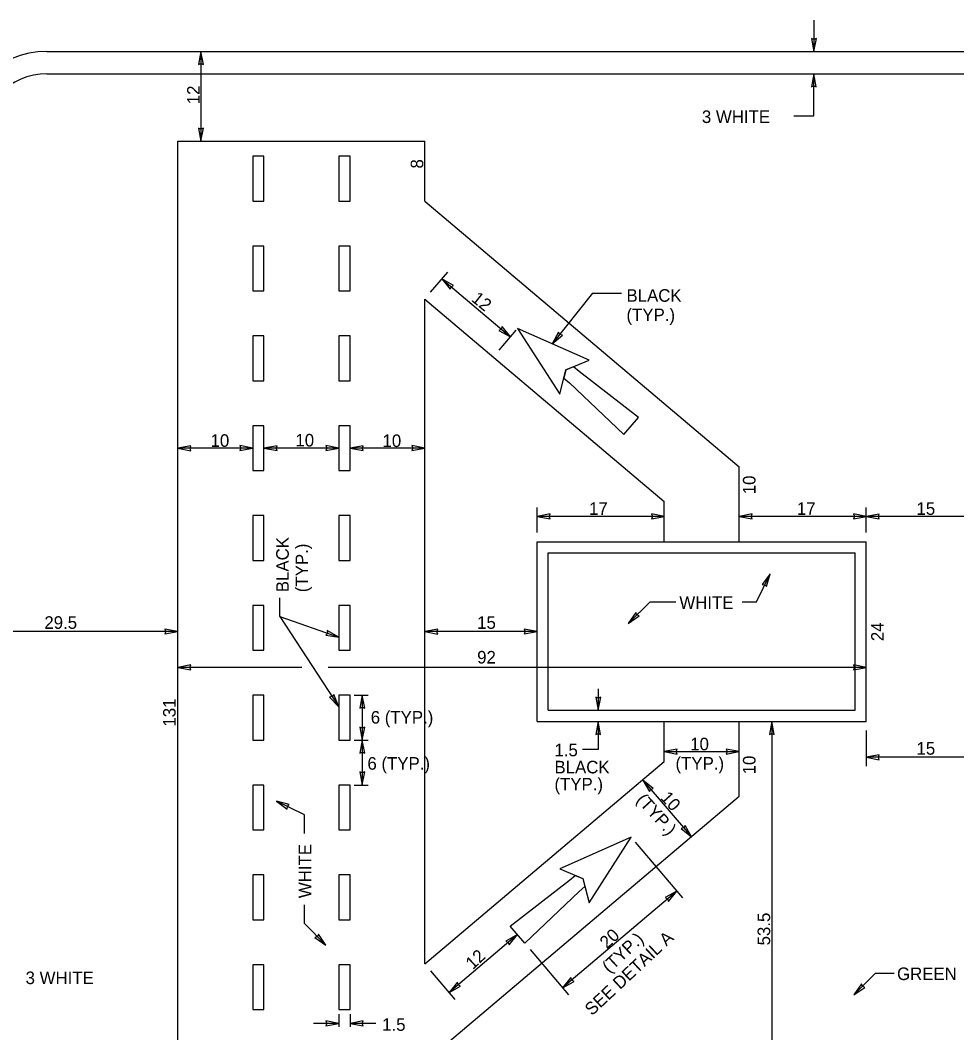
# Model space of a CAD drawing. Extents: x 319701 to 320014, y 1621790 to 1621996.
# Drawn here: x 319807.6 to 319911.9, y 1621877.3 to 1621990 of the extents above; entities that cross this region are included whole.
import ezdxf

# ---------------------------------------------------------------- set-up
doc = ezdxf.new("R2010")
doc.units = 0
for name, color, linetype in [('1', 7, 'Continuous'), ('40', 7, 'Continuous'), ('48', 7, 'Continuous'), ('52', 7, 'Continuous')]:
    doc.layers.add(name, color=color, linetype=linetype)

msp = doc.modelspace()

# ---------------------------------------------------------------- linework, layer by layer
at = {"layer": '1'}
for p, q in [((319810.55, 1621986.54), (319970.55, 1621986.54)), ((319810.55, 1621984.04), (319970.55, 1621984.04)), ((319825.14, 1621976.54), (319852.63, 1621976.54)), ((319825.14, 1621867.37), (319825.14, 1621976.54)), ((319852.63, 1621969.87), (319852.63, 1621976.54)), ((319852.63, 1621969.87), (319887.63, 1621940.29)), ((319852.63, 1621958.96), (319879.3, 1621936.42)), ((319852.63, 1621884.95), (319852.63, 1621958.96)), ((319887.63, 1621931.96), (319887.63, 1621940.29)), ((319879.3, 1621931.96), (319879.3, 1621936.42)), ((319865.13, 1621911.96), (319865.13, 1621931.96)), ((319865.13, 1621931.96), (319901.8, 1621931.96)), ((319901.8, 1621911.96), (319901.8, 1621931.96)), ((319866.38, 1621930.71), (319900.55, 1621930.71)), ((319866.38, 1621913.21), (319866.38, 1621930.71)), ((319900.55, 1621913.21), (319900.55, 1621930.71)), ((319866.38, 1621913.21), (319900.55, 1621913.21)), ((319865.13, 1621911.96), (319901.8, 1621911.96)), ((319879.3, 1621907.49), (319879.3, 1621911.96)), ((319887.63, 1621903.62), (319887.63, 1621911.96)), ((319852.63, 1621884.95), (319879.3, 1621907.49)), ((319852.63, 1621874.04), (319887.63, 1621903.62))]:
    msp.add_line(p, q, dxfattribs=at)
for radius in [10, 7.5]:
    msp.add_arc((319810.55, 1621976.54), radius, 90, 180, dxfattribs=at)
at = {"layer": '40'}
for p, q in [((319834.72, 1621974.87), (319833.47, 1621974.87)), ((319833.47, 1621974.87), (319833.47, 1621969.87)), ((319834.72, 1621969.87), (319834.72, 1621974.87)), ((319844.3, 1621974.87), (319843.05, 1621974.87)), ((319843.05, 1621974.87), (319843.05, 1621969.87)), ((319844.3, 1621969.87), (319844.3, 1621974.87)), ((319833.47, 1621969.87), (319834.72, 1621969.87)), ((319843.05, 1621969.87), (319844.3, 1621969.87)), ((319834.72, 1621964.87), (319833.47, 1621964.87)), ((319833.47, 1621964.87), (319833.47, 1621959.87)), ((319834.72, 1621959.87), (319834.72, 1621964.87)), ((319844.3, 1621964.87), (319843.05, 1621964.87)), ((319843.05, 1621964.87), (319843.05, 1621959.87)), ((319844.3, 1621959.87), (319844.3, 1621964.87)), ((319833.47, 1621959.87), (319834.72, 1621959.87)), ((319843.05, 1621959.87), (319844.3, 1621959.87)), ((319862.96, 1621955.69), (319867.66, 1621948.37)), ((319870.92, 1621952.17), (319862.96, 1621955.69)), ((319834.72, 1621954.87), (319833.47, 1621954.87)), ((319833.47, 1621954.87), (319833.47, 1621949.87)), ((319834.72, 1621949.87), (319834.72, 1621954.87)), ((319844.3, 1621954.87), (319843.05, 1621954.87)), ((319843.05, 1621954.87), (319843.05, 1621949.87)), ((319844.3, 1621949.87), (319844.3, 1621954.87)), ((319868.34, 1621951.08), (319870.92, 1621952.17)), ((319867.66, 1621948.37), (319868.34, 1621951.08)), ((319868.34, 1621951.08), (319868.11, 1621950.18)), ((319869.2, 1621951.44), (319868.34, 1621951.08)), ((319869.83, 1621950.9), (319869.2, 1621951.44)), ((319876.43, 1621945.79), (319869.83, 1621950.9)), ((319833.47, 1621949.87), (319834.72, 1621949.87)), ((319843.05, 1621949.87), (319844.3, 1621949.87)), ((319868.11, 1621950.18), (319868.75, 1621949.63)), ((319868.75, 1621949.63), (319874.8, 1621943.89)), ((319874.8, 1621943.89), (319876.43, 1621945.79)), ((319834.72, 1621944.87), (319833.47, 1621944.87)), ((319833.47, 1621944.87), (319833.47, 1621939.87)), ((319834.72, 1621939.87), (319834.72, 1621944.87)), ((319844.3, 1621944.87), (319843.05, 1621944.87)), ((319843.05, 1621944.87), (319843.05, 1621939.87)), ((319844.3, 1621939.87), (319844.3, 1621944.87)), ((319833.47, 1621939.87), (319834.72, 1621939.87)), ((319843.05, 1621939.87), (319844.3, 1621939.87)), ((319834.72, 1621934.87), (319833.47, 1621934.87)), ((319833.47, 1621934.87), (319833.47, 1621929.87)), ((319834.72, 1621929.87), (319834.72, 1621934.87)), ((319844.3, 1621934.87), (319843.05, 1621934.87)), ((319843.05, 1621934.87), (319843.05, 1621929.87)), ((319844.3, 1621929.87), (319844.3, 1621934.87)), ((319833.47, 1621929.87), (319834.72, 1621929.87)), ((319843.05, 1621929.87), (319844.3, 1621929.87)), ((319834.72, 1621924.87), (319833.47, 1621924.87)), ((319833.47, 1621924.87), (319833.47, 1621919.87)), ((319834.72, 1621919.87), (319834.72, 1621924.87)), ((319844.3, 1621924.87), (319843.05, 1621924.87)), ((319843.05, 1621924.87), (319843.05, 1621919.87)), ((319844.3, 1621919.87), (319844.3, 1621924.87)), ((319833.47, 1621919.87), (319834.72, 1621919.87)), ((319843.05, 1621919.87), (319844.3, 1621919.87)), ((319834.72, 1621914.87), (319833.47, 1621914.87)), ((319833.47, 1621914.87), (319833.47, 1621909.87)), ((319834.72, 1621909.87), (319834.72, 1621914.87)), ((319844.3, 1621914.87), (319843.05, 1621914.87)), ((319843.05, 1621914.87), (319843.05, 1621909.87)), ((319844.3, 1621909.87), (319844.3, 1621914.87)), ((319833.47, 1621909.87), (319834.72, 1621909.87)), ((319843.05, 1621909.87), (319844.3, 1621909.87)), ((319834.72, 1621904.87), (319833.47, 1621904.87)), ((319833.47, 1621904.87), (319833.47, 1621899.87)), ((319834.72, 1621899.87), (319834.72, 1621904.87)), ((319844.3, 1621904.87), (319843.05, 1621904.87)), ((319843.05, 1621904.87), (319843.05, 1621899.87)), ((319844.3, 1621899.87), (319844.3, 1621904.87)), ((319833.47, 1621899.87), (319834.72, 1621899.87)), ((319843.05, 1621899.87), (319844.3, 1621899.87)), ((319875.62, 1621899.07), (319867.66, 1621895.55)), ((319870.92, 1621891.75), (319875.62, 1621899.07)), ((319834.72, 1621894.87), (319833.47, 1621894.87)), ((319833.47, 1621894.87), (319833.47, 1621889.87)), ((319834.72, 1621889.87), (319834.72, 1621894.87)), ((319844.3, 1621894.87), (319843.05, 1621894.87)), ((319843.05, 1621894.87), (319843.05, 1621889.87)), ((319844.3, 1621889.87), (319844.3, 1621894.87)), ((319867.66, 1621895.55), (319870.24, 1621894.46)), ((319868.75, 1621894.28), (319869.38, 1621894.82)), ((319869.38, 1621894.82), (319870.24, 1621894.46)), ((319862.15, 1621889.17), (319868.75, 1621894.28)), ((319870.46, 1621893.56), (319869.83, 1621893.02)), ((319870.24, 1621894.46), (319870.46, 1621893.56)), ((319870.24, 1621894.46), (319870.92, 1621891.75)), ((319869.83, 1621893.02), (319863.77, 1621887.28)), ((319833.47, 1621889.87), (319834.72, 1621889.87)), ((319843.05, 1621889.87), (319844.3, 1621889.87)), ((319863.77, 1621887.28), (319862.15, 1621889.17)), ((319834.72, 1621884.87), (319833.47, 1621884.87)), ((319833.47, 1621884.87), (319833.47, 1621879.87)), ((319834.72, 1621879.87), (319834.72, 1621884.87)), ((319844.3, 1621884.87), (319843.05, 1621884.87)), ((319843.05, 1621884.87), (319843.05, 1621879.87)), ((319844.3, 1621879.87), (319844.3, 1621884.87)), ((319833.47, 1621879.87), (319834.72, 1621879.87)), ((319843.05, 1621879.87), (319844.3, 1621879.87))]:
    msp.add_line(p, q, dxfattribs=at)
at = {"layer": '48'}
for p, q in [((319895.97, 1621990.01), (319895.97, 1621986.54)), ((319827.7, 1621986.54), (319827.7, 1621976.54)), ((319895.97, 1621979.38), (319895.97, 1621984.04)), ((319893.72, 1621979.38), (319895.97, 1621979.38)), ((319853.28, 1621959.73), (319855.18, 1621961.97)), ((319854.53, 1621961.21), (319862.17, 1621954.75)), ((319871.32, 1621959.64), (319866.83, 1621953.98)), ((319871.32, 1621959.64), (319874.53, 1621959.64)), ((319860.92, 1621953.27), (319862.81, 1621955.52)), ((319833.47, 1621942.37), (319825.14, 1621942.37)), ((319843.05, 1621942.37), (319834.72, 1621942.37)), ((319852.63, 1621942.37), (319844.3, 1621942.37)), ((319865.13, 1621932.97), (319865.13, 1621935.78)), ((319901.8, 1621932.97), (319901.8, 1621935.78)), ((319879.3, 1621934.78), (319865.13, 1621934.78)), ((319901.8, 1621934.78), (319887.63, 1621934.78)), ((319914.3, 1621934.78), (319901.8, 1621934.78)), ((319889.57, 1621925.27), (319891.11, 1621928.38)), ((319836.47, 1621923.64), (319836.47, 1621925.71)), ((319877.71, 1621925.27), (319875.29, 1621922.87)), ((319877.71, 1621925.27), (319880.57, 1621925.27)), ((319887.96, 1621925.27), (319889.57, 1621925.27)), ((319836.47, 1621923.64), (319843.05, 1621921.33)), ((319836.47, 1621923.64), (319843.05, 1621913.58)), ((319825.14, 1621921.96), (319800.55, 1621921.96)), ((319865.13, 1621921.96), (319852.63, 1621921.96)), ((319838.93, 1621917.97), (319825.14, 1621917.97)), ((319901.8, 1621917.97), (319841.86, 1621917.97)), ((319844.76, 1621914.87), (319846.33, 1621914.87)), ((319845.66, 1621914.87), (319845.66, 1621909.87)), ((319871.95, 1621915.58), (319871.95, 1621913.21)), ((319871.95, 1621911.96), (319871.95, 1621908.84)), ((319891.29, 1621911.96), (319891.29, 1621867.37)), ((319901.8, 1621910.96), (319901.8, 1621906.98)), ((319844.76, 1621909.87), (319846.33, 1621909.87)), ((319845.66, 1621909.87), (319845.66, 1621904.87)), ((319871.95, 1621908.84), (319870.21, 1621908.84)), ((319879.3, 1621908.59), (319887.63, 1621908.59)), ((319914.3, 1621907.98), (319901.8, 1621907.98)), ((319844.76, 1621904.87), (319846.33, 1621904.87)), ((319876.92, 1621905.42), (319882.34, 1621899.09)), ((319839.23, 1621901.55), (319836.12, 1621903.09)), ((319839.23, 1621899.47), (319839.23, 1621901.55)), ((319876.07, 1621898.53), (319881.34, 1621892.3)), ((319880.7, 1621893.06), (319867.98, 1621882.29)), ((319839.23, 1621889.46), (319839.23, 1621891.53)), ((319839.23, 1621889.46), (319841.62, 1621887.04)), ((319862.96, 1621888.23), (319855.33, 1621881.76)), ((319864.35, 1621886.58), (319868.63, 1621881.52)), ((319853.28, 1621884.19), (319855.98, 1621881)), ((319902.83, 1621883.92), (319900.42, 1621881.53)), ((319902.83, 1621883.92), (319904.91, 1621883.92)), ((319843.05, 1621879.37), (319843.05, 1621877.96)), ((319844.3, 1621879.37), (319844.3, 1621877.96)), ((319843.05, 1621878.33), (319840.24, 1621878.33)), ((319847.17, 1621878.33), (319844.3, 1621878.33))]:
    msp.add_line(p, q, dxfattribs=at)
at = {"layer": '52'}
for p, q in [((319895.96, 1621987.88), (319895.69, 1621987.99)), ((319895.69, 1621987.99), (319895.96, 1621986.54)), ((319895.96, 1621986.54), (319896.24, 1621987.99)), ((319896.24, 1621987.99), (319895.96, 1621987.88)), ((319827.7, 1621986.54), (319827.42, 1621985.09)), ((319827.97, 1621985.09), (319827.7, 1621986.54)), ((319827.42, 1621985.09), (319827.7, 1621985.2)), ((319827.7, 1621985.2), (319827.97, 1621985.09)), ((319895.96, 1621984.04), (319895.68, 1621982.59)), ((319896.23, 1621982.59), (319895.96, 1621984.04)), ((319895.68, 1621982.59), (319895.96, 1621982.7)), ((319895.96, 1621982.7), (319896.23, 1621982.59)), ((319827.7, 1621977.88), (319827.43, 1621977.99)), ((319827.43, 1621977.99), (319827.7, 1621976.54)), ((319827.7, 1621976.54), (319827.98, 1621977.99)), ((319827.98, 1621977.99), (319827.7, 1621977.88)), ((319854.53, 1621961.21), (319855.45, 1621960.06)), ((319855.81, 1621960.48), (319854.53, 1621961.21)), ((319855.45, 1621960.06), (319855.55, 1621960.34)), ((319855.55, 1621960.34), (319855.81, 1621960.48)), ((319861.14, 1621955.62), (319860.88, 1621955.48)), ((319860.88, 1621955.48), (319862.16, 1621954.75)), ((319861.24, 1621955.9), (319861.14, 1621955.62)), ((319862.16, 1621954.75), (319861.24, 1621955.9)), ((319867.51, 1621955.28), (319866.83, 1621953.98)), ((319866.83, 1621953.98), (319867.95, 1621954.94)), ((319867.66, 1621955.03), (319867.51, 1621955.28)), ((319867.95, 1621954.94), (319867.66, 1621955.03)), ((319826.59, 1621942.64), (319825.14, 1621942.37)), ((319825.14, 1621942.37), (319826.59, 1621942.09)), ((319826.48, 1621942.37), (319826.59, 1621942.64)), ((319826.59, 1621942.09), (319826.48, 1621942.37)), ((319833.47, 1621942.38), (319832.02, 1621942.66)), ((319832.02, 1621942.66), (319832.13, 1621942.38)), ((319832.13, 1621942.38), (319832.02, 1621942.11)), ((319832.02, 1621942.11), (319833.47, 1621942.38)), ((319836.17, 1621942.65), (319834.72, 1621942.38)), ((319834.72, 1621942.38), (319836.17, 1621942.1)), ((319836.06, 1621942.38), (319836.17, 1621942.65)), ((319836.17, 1621942.1), (319836.06, 1621942.38)), ((319843.05, 1621942.38), (319841.6, 1621942.66)), ((319841.6, 1621942.66), (319841.71, 1621942.38)), ((319841.71, 1621942.38), (319841.6, 1621942.11)), ((319841.6, 1621942.11), (319843.05, 1621942.38)), ((319845.75, 1621942.65), (319844.3, 1621942.38)), ((319844.3, 1621942.38), (319845.75, 1621942.1)), ((319845.64, 1621942.38), (319845.75, 1621942.65)), ((319845.75, 1621942.1), (319845.64, 1621942.38)), ((319852.63, 1621942.38), (319851.18, 1621942.66)), ((319851.18, 1621942.66), (319851.29, 1621942.38)), ((319851.29, 1621942.38), (319851.18, 1621942.11)), ((319851.18, 1621942.11), (319852.63, 1621942.38)), ((319866.58, 1621935.05), (319865.13, 1621934.78)), ((319865.13, 1621934.78), (319866.58, 1621934.5)), ((319866.47, 1621934.78), (319866.58, 1621935.05)), ((319866.58, 1621934.5), (319866.47, 1621934.78)), ((319879.31, 1621934.78), (319877.86, 1621935.06)), ((319877.86, 1621935.06), (319877.97, 1621934.78)), ((319877.97, 1621934.78), (319877.86, 1621934.51)), ((319877.86, 1621934.51), (319879.31, 1621934.78)), ((319889.08, 1621935.05), (319887.63, 1621934.78)), ((319887.63, 1621934.78), (319889.08, 1621934.5)), ((319888.97, 1621934.78), (319889.08, 1621935.05)), ((319889.08, 1621934.5), (319888.97, 1621934.78)), ((319901.81, 1621934.78), (319900.36, 1621935.06)), ((319900.36, 1621935.06), (319900.47, 1621934.78)), ((319900.47, 1621934.78), (319900.36, 1621934.51)), ((319900.36, 1621934.51), (319901.81, 1621934.78)), ((319903.25, 1621935.04), (319901.8, 1621934.77)), ((319901.8, 1621934.77), (319903.25, 1621934.49)), ((319903.14, 1621934.77), (319903.25, 1621935.04)), ((319903.25, 1621934.49), (319903.14, 1621934.77)), ((319891.1, 1621928.37), (319890.2, 1621927.2)), ((319890.7, 1621926.96), (319891.1, 1621928.37)), ((319890.2, 1621927.2), (319890.5, 1621927.17)), ((319890.5, 1621927.17), (319890.7, 1621926.96)), ((319876.13, 1621924.09), (319875.29, 1621922.87)), ((319876.24, 1621923.82), (319876.13, 1621924.09)), ((319876.52, 1621923.69), (319876.24, 1621923.82)), ((319875.29, 1621922.87), (319876.52, 1621923.69)), ((319825.14, 1621921.96), (319823.69, 1621922.24)), ((319823.69, 1621922.24), (319823.8, 1621921.96)), ((319823.8, 1621921.96), (319823.69, 1621921.69)), ((319823.69, 1621921.69), (319825.14, 1621921.96)), ((319841.78, 1621921.78), (319841.59, 1621921.56)), ((319841.59, 1621921.56), (319843.05, 1621921.34)), ((319843.05, 1621921.34), (319841.77, 1621922.08)), ((319841.77, 1621922.08), (319841.78, 1621921.78)), ((319854.08, 1621922.23), (319852.63, 1621921.96)), ((319852.63, 1621921.96), (319854.08, 1621921.68)), ((319853.97, 1621921.96), (319854.08, 1621922.23)), ((319854.08, 1621921.68), (319853.97, 1621921.96)), ((319865.14, 1621921.96), (319863.69, 1621922.24)), ((319863.69, 1621922.24), (319863.8, 1621921.96)), ((319863.8, 1621921.96), (319863.69, 1621921.69)), ((319863.69, 1621921.69), (319865.14, 1621921.96)), ((319826.58, 1621918.24), (319825.13, 1621917.97)), ((319826.47, 1621917.97), (319826.58, 1621918.24)), ((319901.81, 1621917.97), (319900.36, 1621918.25)), ((319900.36, 1621918.25), (319900.47, 1621917.97)), ((319825.13, 1621917.97), (319826.58, 1621917.69)), ((319826.58, 1621917.69), (319826.47, 1621917.97)), ((319900.47, 1621917.97), (319900.36, 1621917.7)), ((319900.36, 1621917.7), (319901.81, 1621917.97)), ((319842.49, 1621914.96), (319842.32, 1621914.71)), ((319843.05, 1621913.59), (319842.49, 1621914.96)), ((319845.67, 1621914.88), (319845.39, 1621913.43)), ((319845.94, 1621913.43), (319845.67, 1621914.88)), ((319842.32, 1621914.71), (319842.03, 1621914.66)), ((319842.03, 1621914.66), (319843.05, 1621913.59)), ((319871.94, 1621914.54), (319871.67, 1621914.65)), ((319871.67, 1621914.65), (319871.94, 1621913.2)), ((319871.94, 1621913.2), (319872.22, 1621914.65)), ((319872.22, 1621914.65), (319871.94, 1621914.54)), ((319845.39, 1621913.43), (319845.67, 1621913.54)), ((319845.67, 1621913.54), (319845.94, 1621913.43)), ((319871.94, 1621911.96), (319871.66, 1621910.51)), ((319872.21, 1621910.51), (319871.94, 1621911.96)), ((319891.28, 1621911.96), (319891, 1621910.51)), ((319891.55, 1621910.51), (319891.28, 1621911.96)), ((319845.67, 1621911.22), (319845.4, 1621911.33)), ((319845.4, 1621911.33), (319845.67, 1621909.88)), ((319845.67, 1621909.88), (319845.95, 1621911.33)), ((319845.95, 1621911.33), (319845.67, 1621911.22)), ((319871.66, 1621910.51), (319871.94, 1621910.62)), ((319871.94, 1621910.62), (319872.21, 1621910.51)), ((319891, 1621910.51), (319891.28, 1621910.62)), ((319891.28, 1621910.62), (319891.55, 1621910.51)), ((319845.67, 1621909.88), (319845.39, 1621908.43)), ((319845.94, 1621908.43), (319845.67, 1621909.88)), ((319845.39, 1621908.43), (319845.67, 1621908.54)), ((319845.67, 1621908.54), (319845.94, 1621908.43)), ((319880.75, 1621908.86), (319879.3, 1621908.59)), ((319879.3, 1621908.59), (319880.75, 1621908.31)), ((319880.64, 1621908.59), (319880.75, 1621908.86)), ((319880.75, 1621908.31), (319880.64, 1621908.59)), ((319887.63, 1621908.59), (319886.18, 1621908.87)), ((319886.18, 1621908.87), (319886.29, 1621908.59)), ((319886.29, 1621908.59), (319886.18, 1621908.32)), ((319886.18, 1621908.32), (319887.63, 1621908.59)), ((319903.25, 1621908.24), (319901.8, 1621907.97)), ((319903.14, 1621907.97), (319903.25, 1621908.24)), ((319901.8, 1621907.97), (319903.25, 1621907.69)), ((319903.25, 1621907.69), (319903.14, 1621907.97)), ((319845.67, 1621906.22), (319845.4, 1621906.33)), ((319845.4, 1621906.33), (319845.67, 1621904.88)), ((319845.67, 1621904.88), (319845.95, 1621906.33)), ((319845.95, 1621906.33), (319845.67, 1621906.22)), ((319876.92, 1621905.42), (319877.65, 1621904.14)), ((319878.07, 1621904.5), (319876.92, 1621905.42)), ((319877.65, 1621904.14), (319877.79, 1621904.4)), ((319877.79, 1621904.4), (319878.07, 1621904.5)), ((319836.12, 1621903.09), (319837.29, 1621902.19)), ((319837.53, 1621902.69), (319836.12, 1621903.09)), ((319837.29, 1621902.19), (319837.32, 1621902.49)), ((319837.32, 1621902.49), (319837.53, 1621902.69)), ((319881.61, 1621900.38), (319881.47, 1621900.11)), ((319882.34, 1621899.09), (319881.61, 1621900.38)), ((319881.47, 1621900.11), (319881.19, 1621900.02)), ((319881.19, 1621900.02), (319882.34, 1621899.09)), ((319880.69, 1621893.06), (319879.41, 1621892.34)), ((319879.41, 1621892.34), (319879.67, 1621892.19)), ((319879.76, 1621891.92), (319880.69, 1621893.06)), ((319879.67, 1621892.19), (319879.76, 1621891.92)), ((319840.67, 1621888), (319840.4, 1621887.89)), ((319840.4, 1621887.89), (319841.62, 1621887.05)), ((319840.8, 1621888.28), (319840.67, 1621888)), ((319841.62, 1621887.05), (319840.8, 1621888.28)), ((319862.96, 1621888.23), (319861.67, 1621887.5)), ((319862.02, 1621887.08), (319862.96, 1621888.23)), ((319861.67, 1621887.5), (319861.93, 1621887.36)), ((319861.93, 1621887.36), (319862.02, 1621887.08)), ((319868.91, 1621883.43), (319867.98, 1621882.29)), ((319869, 1621883.15), (319868.91, 1621883.43)), ((319856.26, 1621882.91), (319855.33, 1621881.76)), ((319855.33, 1621881.76), (319856.61, 1621882.49)), ((319856.35, 1621882.63), (319856.26, 1621882.91)), ((319856.61, 1621882.49), (319856.35, 1621882.63)), ((319867.98, 1621882.29), (319869.26, 1621883.01)), ((319869.26, 1621883.01), (319869, 1621883.15)), ((319901.25, 1621882.75), (319900.41, 1621881.53)), ((319900.41, 1621881.53), (319901.64, 1621882.35)), ((319901.36, 1621882.48), (319901.25, 1621882.75)), ((319901.64, 1621882.35), (319901.36, 1621882.48)), ((319843.05, 1621878.34), (319841.6, 1621878.62)), ((319841.6, 1621878.62), (319841.71, 1621878.34)), ((319841.71, 1621878.34), (319841.6, 1621878.07)), ((319841.6, 1621878.07), (319843.05, 1621878.34)), ((319845.75, 1621878.61), (319844.3, 1621878.34)), ((319844.3, 1621878.34), (319845.75, 1621878.06)), ((319845.64, 1621878.34), (319845.75, 1621878.61)), ((319845.75, 1621878.06), (319845.64, 1621878.34))]:
    msp.add_line(p, q, dxfattribs=at)

# ---------------------------------------------------------------- texts
at = {"layer": '48'}
for s, rotation, p in [('12', 90, (319827.56, 1621980.66)), ('8', 90, (319852.46, 1621973.5)), ('12', 321.237, (319857.72, 1621958.82)), ('10', 90, (319889.46, 1621937.24)), ('BLACK', 90, (319837.48, 1621926.34)), ('(TYP.)', 90, (319839.63, 1621926.34)), ('24', 90, (319903.74, 1621920.89)), ('131', 90, (319824.88, 1621911.38)), ('10', 90, (319889.46, 1621906.06)), ('(TYP.)', 312.4213, (319876.1, 1621903.15)), ('10', 312.4213, (319878.8, 1621903.39)), ('WHITE', 90, (319839.99, 1621892.28)), ('53.5', 90, (319891.09, 1621887.02)), ('SEE DETAIL A', 43.0352, (319871.25, 1621879.13)), ('20', 43.0352, (319872.91, 1621886.57)), ('(TYP.)', 43.0352, (319873.17, 1621883.87)), ('12', 43.0352, (319857.97, 1621884.26))]:
    msp.add_text(s, height=1.4, rotation=rotation, dxfattribs=at).set_placement(p)
for s, p in [('3 WHITE', (319883.49, 1621978.57)), ('BLACK', (319875.09, 1621958.67)), ('(TYP.)', (319875.09, 1621956.52)), ('10', (319828.77, 1621942.52)), ('10', (319838.22, 1621942.56)), ('10', (319847.92, 1621942.5)), ('17', (319870.92, 1621934.95)), ('17', (319894.07, 1621934.95)), ('15', (319907.39, 1621934.95)), ('WHITE', (319880.98, 1621924.48)), ('29.5', (319810.26, 1621922.26)), ('15', (319858.46, 1621922.26)), ('92', (319858.46, 1621918.4)), ('6 (TYP.)', (319846.61, 1621911.71)), ('1.5', (319867.07, 1621908.07)), ('10', (319882.19, 1621908.74)), ('15', (319907.39, 1621908.25)), ('6 (TYP.)', (319846.24, 1621906.58)), ('(TYP.)', (319880.55, 1621906.59)), ('BLACK', (319867.07, 1621906.17)), ('(TYP.)', (319867.07, 1621904.27)), ('GREEN', (319905.22, 1621883.16)), ('3 WHITE', (319808.17, 1621882.71)), ('1.5', (319847.88, 1621877.51))]:
    msp.add_text(s, height=1.4, dxfattribs=at).set_placement(p)

doc.saveas('drawing.dxf')
